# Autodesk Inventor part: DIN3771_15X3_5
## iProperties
Created: 2012-08
Part Number: DIN3771_15X3_5
Document SubType Name: Modeling
Designer: Administrator
Density: 0.93 g/cm^3
Material: Rubber
Mass: 0.520033 g
Surface Area: 6.39057 cm^2
Volume: 0.559175 cm^3
Author: Administrator
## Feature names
1. Base1
